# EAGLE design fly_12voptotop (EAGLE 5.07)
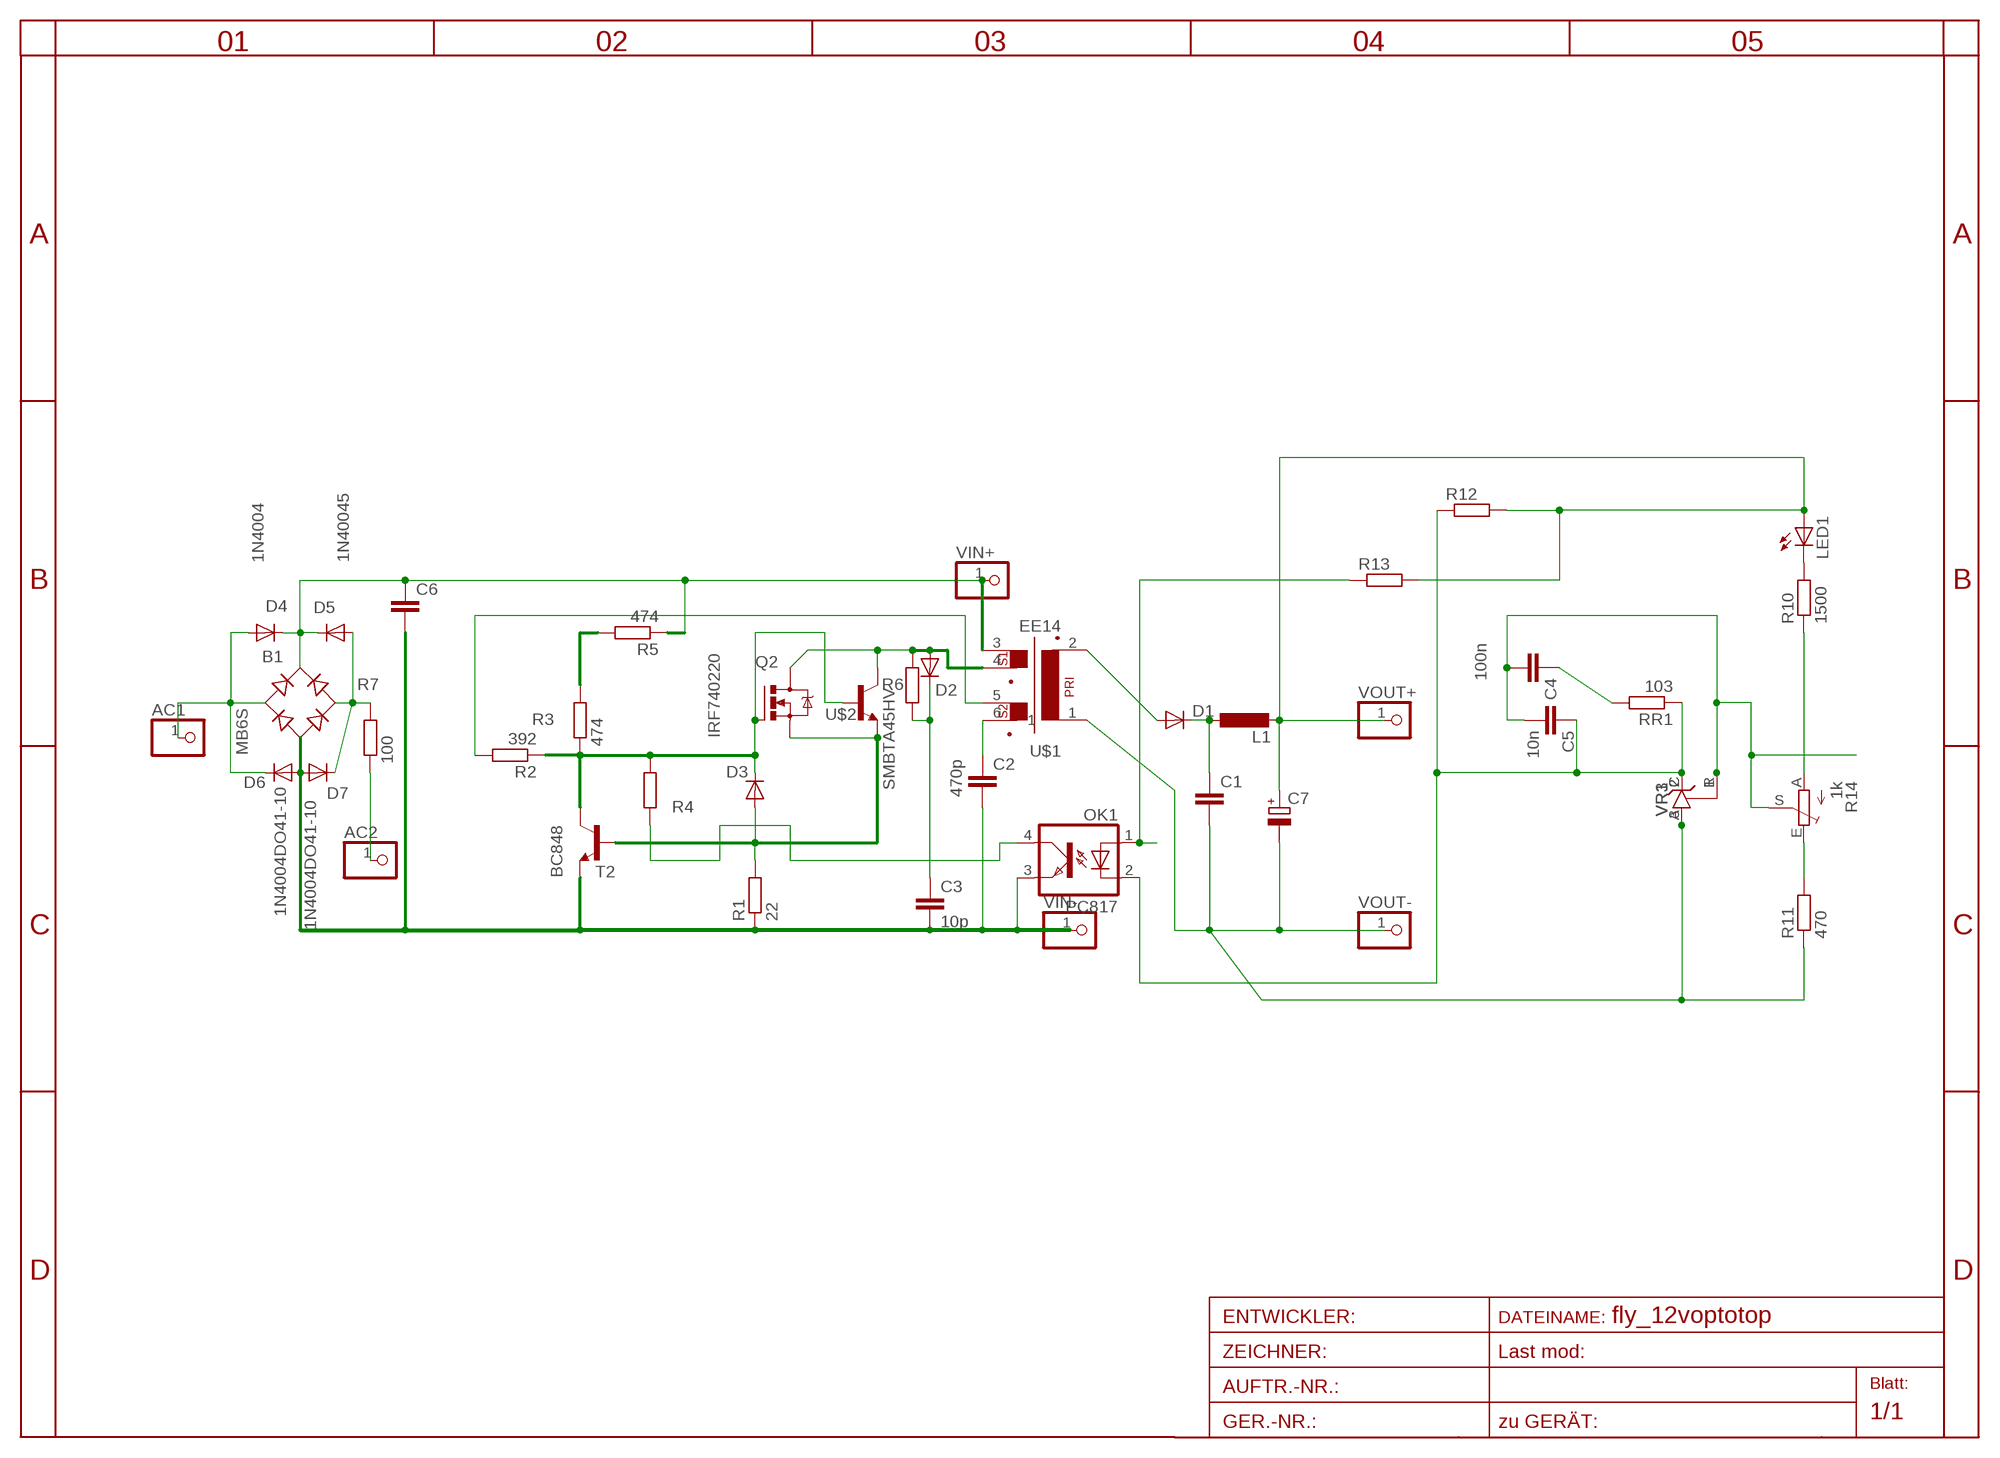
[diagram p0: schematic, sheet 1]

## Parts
AC1  PINHD-1X11MM6  [1X1MM8]
AC2  PINHD-1X11MM6  [1X1MM8]
B1  MB6S  [SOIC-4]
C1  C-EUC0805  [C0805]
C2  470p  C-EUC0805  [C0805]
C3  10p  C-EU050-025X075  [C050-025X075]
C4  100n  C-EUC0805  [C0805]
C5  10n  C-EUC0805  [C0805]
C6  C-EU050-025X075  [C050-025X075]
C7  CPOL-EUE2.5-7  [E2,5-7]
D1  DIODE-SMA-DO214  [SMA-DO214AC]
D2  DIODE-D-5  [D-5]
D3  DIODE-MINIMELF  [MINIMELF]
D4  1N4004  [D-7.5]
D5  1N40045  [C1702-05]
D6  1N4004DO41-10  [DO41-10]
D7  1N4004DO41-10  [DO41-10]
L1  L-EU0204V  [0204V]
LED1  LED3MM  [LED3MM]
OK1  PC817  [DIL04]
Q2  IRF740220  [TO220BV]
R1  22  R-EU_0204/3  [0204/3]
R2  392  R-EU_R0805  [R0805]
R3  474  R-EU_R1206  [R1206]
R4  R-EU_R0805  [R0805]
R5  474  R-EU_R1206  [R1206]
R6  R-EU_0204/5  [0204/5]
R7  100  R-EU_0204/3  [0204/3]
R10  1500  R-EU_R0805  [R0805]
R11  470  R-EU_R1206  [R1206]
R12  R-EU_R0805  [R0805]
R13  R-EU_R0805  [R0805]
R14  1k  TRIM_EU-S64W  [S64W]
RR1  103  R-EU_R0805  [R0805]
T2  BC848  [SOT23]
U$1  EE14  EE14EE20G  [EE20GREEN]
U$2  SMBTA45HV  [SOT23HV]
VIN+  PINHD-1X11MM6  [1X1MM8]
VIN-  PINHD-1X11MM6  [1X1MM8]
VOUT+  PINHD-1X11MM6  [1X1MM8]
VOUT-  PINHD-1X11MM6  [1X1MM8]
VR1  TL431CLPSOT23  [SOT23]
VR3  TL431CLPTO  [TO92-CLP]

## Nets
A: R10.1 R14.A
AC1: AC1.1 B1.~1(AC1) D4.A D6.C
AC2: AC2.1 R7.1
AC3: B1.~2(AC2) D5.A D7.C R7.2
B1C2: D3.C Q2.G R2.1 R3.1 R4.2 T2.C U$2.1(B)
C1: D2.A Q2.D R6.2 U$1.4 U$2.3(C)
E: R11.2 R14.E
EB: D3.A Q2.S R1.2 T2.B U$2.2(E)
K9: C1.1 D1.K(C) L1.1
L3DOT: D1.A U$1.2
N$1: R3.2 R5.2
N$2: R2.2 U$1.5
N$3: C2.1 U$1.6
N$4: LED1.K(C) R10.2
N$5: OK1.4(COL) R4.1
N$6: C3.1 D2.C R6.1
N$7: C5.1 OK1.2(C) R12.1 RR1.1 VR1.2(C) VR3.C
N$8: OK1.1(A) R13.1
N$13: C4.1 RR1.2
OUTMINUS: C1.2 C7.- R11.1 U$1.1 VOUT-.1 VR1.3(A) VR3.A
S: C4.2 C5.2 R14.S VR1.1(R) VR3.R
V+: B1.+ C6.1 D4.C D5.C R5.1 U$1.3 VIN+.1
V-: B1.- C2.2 C3.2 C6.2 D6.A D7.A OK1.3(EMIT) R1.1 T2.E VIN-.1
VOUT+: C7.+ L1.2 LED1.A R12.2 R13.2 VOUT+.1

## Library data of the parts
AC1 AC2 VIN+ VIN- VOUT+ VOUT- = pinhead:PINHD-1X1: PIN HEADER
B1 = rectifier:MB*S: Bridge Rectifier Source: http://www.fairchildsemi.com/ds/MB/MB6S.pdf
C1-C6 = rcl:C-EU: CAPACITOR, European symbol
C7 = rcl:CPOL-EU: POLARIZED CAPACITOR, European symbol
D1-D3 = diode:DIODE-: DIODE
D4-D7 = diode:1N4004: DIODE
L1 = rcl:L-EU: INDUCTOR, European symbol
LED1 = led:LED: LED
OK1 = optocoupler:PC817: SHARP OPTO COUPLER
Q2 = transistor-power:IRF740: N-CHANNEL MOS FET
R1-R7 R10-R13 RR1 = rcl:R-EU_: RESISTOR, European symbol
R14 = pot:TRIM_EU-: POTENTIOMETER
T2 = transistor:BC848: NPN TRANSISTOR
U$1 = trafo:EE14
U$2 = transistor-npn:SMBTA45
VR1 VR3 = v-reg:TL431CLP: VOLTAGE REGULATOR

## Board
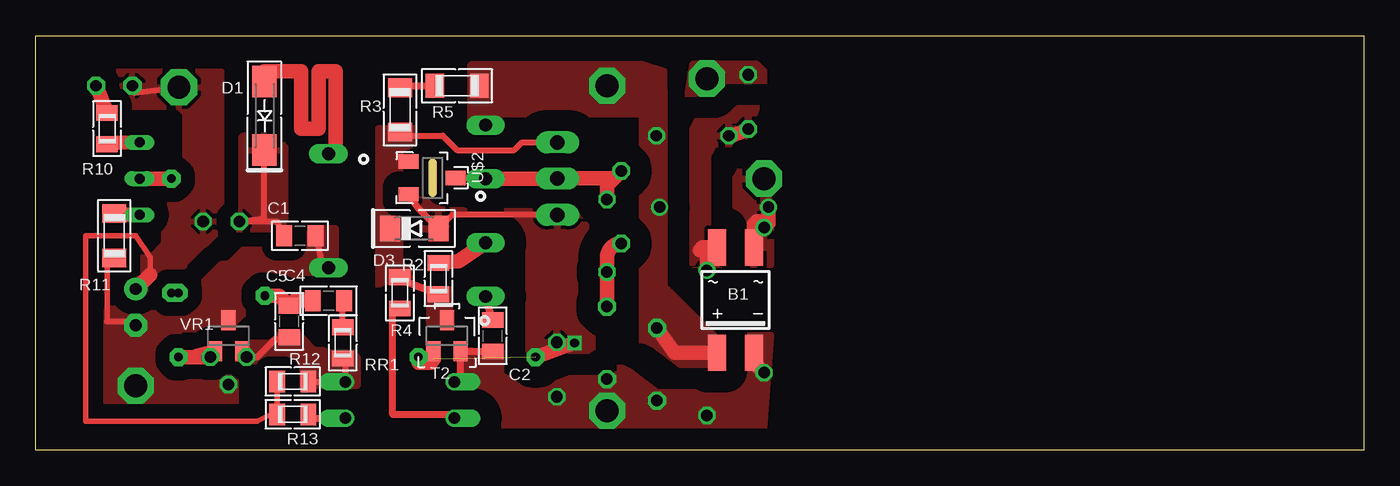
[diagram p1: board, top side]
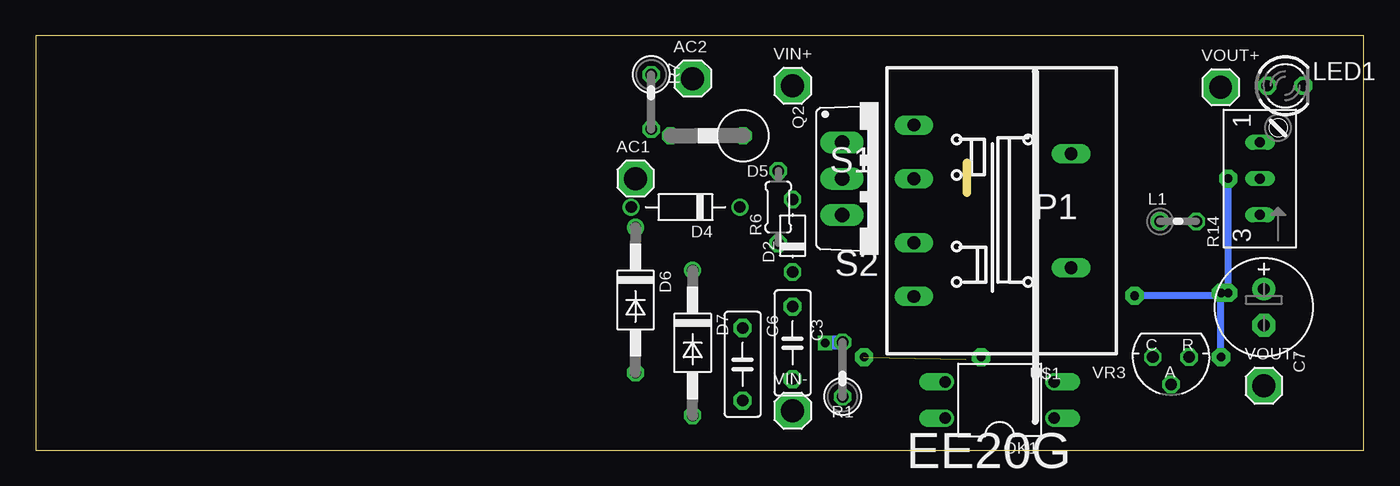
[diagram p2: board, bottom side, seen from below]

Size 93 x 29 mm. Coordinates in mm from the lower left corner, seen from the top.
Outline: 0,29 93,29 93,0 0,0 0,29
Copper layers (1*16): Top 0.035mm / dielectric 1.5mm / Bottom 0.035mm
Design rules "default *": minimum track width 10mil, minimum drill 20mil, track to track 8mil, track to pad 8mil, pad to pad 8mil, via to via 8mil, smd to smd 8mil, copper to edge 40mil, drill to drill 8mil, minimum pad ring 5mil, minimum via ring 8mil, stop-mask expansion 4mil, vias tented up to drill 0mil, thermal gap 10mil

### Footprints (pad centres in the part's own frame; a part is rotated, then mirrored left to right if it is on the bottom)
1X1MM8 = drill 1.6 pad 2.54 octagon: 1 0,0
SOIC-4 = smd 1.27 x 2.54: + 1.3,3.685; - -1.3,3.685; ~1 -1.3,-3.685; ~2 1.3,-3.685
C0805 = smd 1.1 x 1.5: 1 -1.1,0; 2 1.1,0
C050-025X075 = drill 0.8 pad 1.27 octagon: 1 -2.54,0; 2 2.54,0
E2,5-7 = drill 0.813 pad 1.6 round: + -1.27,0 | drill 0.813 pad 1.6 octagon: - 1.27,0
SMA-DO214AC = smd 2.2 x 1.7: A 2.4,0; K -2.4,0
D-5 = drill 0.8 octagon: A 2.54,0; C -2.54,0
MINIMELF = smd 1.4 x 1.8: A 1.7,0; C -1.7,0
D-7.5 = drill 0.8 round: A 3.81,0; C -3.81,0
C1702-05 = drill 0.8 octagon: A 2.54,0; C -2.54,0
DO41-10 = drill 0.8 octagon: A 5.08,0 | drill 0.8 round: C -5.08,0
0204V = drill 0.813 octagon: 1 -1.27,0; 2 1.27,0
LED3MM = drill 0.8 pad 1.27 octagon: A -1.27,0; K 1.27,0
DIL04 = drill 0.813 offset: 1 -1.27,-3.81; 2 1.27,-3.81; 3 1.27,3.81; 4 -1.27,3.81
TO220BV = drill 1.016 long: D 0,-2.54; G -2.54,-2.54; S 2.54,-2.54
0204/3 = drill 0.813 octagon: 1 -1.27,0; 2 2.54,0
R0805 = smd 1.1 x 1.5: 1 -1.1,0; 2 1.1,0
R1206 = smd 1.3 x 1.7: 1 -1.55,0; 2 1.55,0
0204/5 = drill 0.813 octagon: 1 -2.54,0; 2 2.54,0
S64W = drill 0.7 long: A 2.54,1.27; E -2.54,1.27; S 0,1.27
SOT23 = smd 1 x 1.4: B -0.95,-1.1; C 0,1.1; E 0.95,-1.1
EE20GREEN = drill 0.9 pad 1.2 long: 1 5.5,-4; 2 5.5,4; 3 -5.5,6; 4 -5.5,2.25; 5 -5.5,-2.25; 6 -5.5,-6
SOT23HV = smd 1 x 1.4: 1 -1.15,-1.7; 2 1.15,-1.7; 3 0,1.6
SOT23' = smd 1 x 1.4: 1 -0.95,-1.1; 2 0.95,-1.1; 3 0,1.1
TO92-CLP = drill 0.813 octagon: A 0,1.905; C 1.27,0; R -1.27,0

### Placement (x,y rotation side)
AC1  51,19 0 bottom
AC2  47,26 0 bottom
B1  49,10.5 180 top
C1  18.5,15 0 top
C2  32,8 270 top
C3  40,7.5 270 bottom
C4  20.5,10.45 180 top
C5  17.75,9 90 top
C6  43.5,6 270 bottom
C7  7,10 270 bottom
D1  16.01,23.39 90 top
D2  40,15 90 bottom
D3  26.5,15.5 0 top
D4  47.5,17 180 bottom
D5  46,22 180 bottom
D6  51,10.5 270 bottom
D7  47,7.5 270 bottom
L1  13,16 0 bottom
LED1  5.5,25.5 0 bottom
OK1  25.5,3.5 90 bottom
Q2  34,19 270 bottom
R1  36.5,5 90 bottom
R2  28.2,12 90 top
R3  25.51,23.81 90 top
R4  25.5,11 90 top
R5  29.5,25.5 180 top
R6  41,17 90 bottom
R7  49.9,25 270 bottom
R10  5,22.5 90 top
R11  5.5,15 90 top
R12  18,4.8 180 top
R13  18,2.5 180 top
R14  6,19 90 bottom
RR1  21.5,7.5 90 top
T2  28.8,8 0 top
U$1  26,16.75 0 bottom
U$2  27.8,19.05 270 top
VIN+  40,25.5 0 bottom
VIN-  40,2.75 0 bottom
VOUT+  10.03,25.39 0 bottom
VOUT-  7,4.5 0 bottom
VR1  [SOT23']  13.5,8 0 top
VR3  13.5,6.5 180 bottom

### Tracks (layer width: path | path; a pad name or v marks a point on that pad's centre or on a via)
A
  Top 1: R10.1 5.73,21.5 R14.A
AC1
  Top 1: D4.A 51.31,15.89 D6.C 50.58,16 50.5,16 50.3,15.8 B1.~1
  pour Top (isolate 1.5): 51.5,20 49.5,20 49,19 49,13 51.5,13
AC2
  pour Top (isolate 1.5, rank 3, no thermals): 45.5,24 50.5,24 51,24.5 51,26.5 50.5,27 46,27
AC3
  Top 1: 47,14.19 B1.~2 | 47,14.19 46.69,14.19 46.5,14 | D5.A 48.77,22 R7.2 | D7.C 47,14.19
  pour Top (isolate 1.5, rank 2): 48.5,13.5 49.5,21.5 50.5,24 47,24 46.5,23.5 46,22.5 46,13 48,13
B1C2
  Top 0.406: Q2.G 34.04,21.54 33.5,21 29.5,21 28.5,22 25.77,22 R3.1
  Top 0.5: R2.1 25.7,11.9 R4.2
  pour Top (isolate 1.1, no thermals): 26.5,22.5 24,22.5 24,11 27,8.5 28.5,8.5 29,9 29,11.5 27.5,11.5 25.5,13 25.5,21 26.5,21.5
C1
  Top 0.5: U$1.4 31.4,19.1 | U$2.3 31.95,19.05 32,19
  Top 1: U$1.4 32,19 Q2.D 36.58,19.04 40.5,19.04 | 40.5,19.04 R6.2 | D2.A 40,18.54 40.5,19.04
E
  Top 0.406: R11.2 5.86,16.46
  Top 1: 5.86,16.46 R14.E
EB  (via drill 0.6, 0.6 pad 1.27)  (1 unrouted)
  Top 0.406: 27.8,15.9 D3.A 29.2,16.5 36.5,16.5 Q2.S
  Top 0.5: U$2.2 26.8,16.9 27.8,15.9
  Top 1: T2.B 27.85,6.35 27.7,6.1 26.8,6.1 v26.8,6.5 | v35,6.5 v37.73,7.5
  Bottom 1: v37.73,7.5 R1.2
  pour Top (isolate 1.5): 39,7 39,16 37.5,17.5 26.5,17.5 26.5,15 34.5,15.5 34.5,7
K9
  Top 0.406: D1.K 15.85,20.84 16,20.5 16,16.23 L1.1 16.9,16 C1.1
  pour Top (isolate 1, rank 3): 17.5,22 14.5,22 14,21.5 14,14.5 17.5,14.5
L3DOT
  Top 1.016: U$1.2 21,20.75 21,26.5 19.8,26.5 19.8,22.5 18.6,22.5 18.6,26.5 16,26.5 arc-90 16.14,26.36 D1.A
N$1
  Top 0.5: R5.2 25.65,25.5 R3.2
N$2
  Top 0.5: U$1.5 30.9,14.5
  Top 1: R2.2 29.6,13.2 U$1.5
N$3
  Top 0.5: C2.1 U$1.6
N$4
  Top 1: R10.2 LED1.K
N$5
  Top 0.5: R4.1 25,9.9 25,2.5 29.04,2.5 OK1.4
N$6
  Top 1: R6.1 arc90 40,13.46 D2.C C3.1
N$7
  Top 0.406: RR1.1 21.69,6.21 OK1.2 19.5,4.77 19.27,4.77 19,4.5 | VR3.C 15.5,6.5
  Top 0.5: C5.1 16.75,7.75 15.5,6.5 | R12.1 19.47,4.8 19.5,4.77
  Top 1: VR3.C 14.77,6.58 VR1.2
  pour Top (isolate 1, rank 2, no thermals): 15,7.5 16.5,7.5 17,8 18.5,8 19.5,7 22,7 22.5,6.5 22.5,4.5 18.5,4.5 18.5,5.5 18,6 15,6
N$8
  Top 0.5: OK1.1 19.37,2.23 R13.1
N$13
  Top 0.406: RR1.2 21.5,9.9 C4.1
OUTMINUS
  Top 0.4: 5,9 5,13.5 5.45,13.5 R11.1
  Top 0.406: C1.2 20,13.25 U$1.1 | 5,9 6.73,9 C7.-
  pour Top (isolate 1, no thermals): 21,15.5 19.5,15.5 18,14 14.5,14 13.5,13 13,13 10,10 5.5,10 4.5,9.5 4.5,4 5,3 14,3 14,5.5 13.5,6 10.5,6 10,6.5 10,8.5 13.5,8.5 14.5,9.5 14.5,11 21,11
S  (via drill 0.6 pad 1.27)
  Top 0.5: v10,11 v9.5,11
  Top 1: v9.5,19 R14.S | v10,6.5 VR3.R 11.23,6.58 VR1.1 | v16.05,10.8 17.05,10.8 C5.2 18.1,10.45 C4.2
  Bottom 0.5: 10,10.8 v16.05,10.8 | 10,10.8 v10,11 | v9.5,11 v9.5,19 | v10,6.5 10,10.8
V+
  Top 1: B1.+ 44.73,6.82 C6.1
  pour Top (isolate 1.5, rank 3, no thermals): 30.5,22.5 30.5,27 42.5,27 44,26.5 44,11.5 47.5,8 47.5,5.5 43,5.5 42.5,6 42.5,23.5 32.5,23.5 32,23
V-
  Top 0.5: OK1.3 29.58,4.5 30,4.5 29.75,4.75 T2.E C2.2
  Top 1: B1.- 50.3,6.12 D6.A
  pour Top (isolate 1.5, rank 2, no thermals): 51.5,8 49,8 48.5,7.5 48.5,5 47.5,4 43.5,4 41.5,5.5 40.5,6 37.5,6 28,8 28,2.5 28.5,1.5 51,1.5
VOUT+
  Top 0.4: 8,12.27 8,13.5 7,15 3.5,15 3.5,2 15.5,2 16.5,2.5 R13.2 R12.2
  Top 0.406: L1.2 11.5,15.73 | 6.92,25 VOUT+.1
  Top 1: 8,12.27 C7.+
  pour Top (isolate 1, rank 2): 4,26.5 13,26.5 13,15.5 7.5,10 6,10 5,11 5,13.5 8,13.5 9,14.5 9,18.5 10.5,20 10.5,23.5 10,24 4,24 3.5,23.5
